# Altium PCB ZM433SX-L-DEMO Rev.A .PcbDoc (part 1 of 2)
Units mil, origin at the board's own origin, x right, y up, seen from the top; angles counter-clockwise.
Board outline 3937.01 x 2559.06 mil, 2 copper layers (Top Layer, Bottom Layer); 88 components, 121 nets, 406 pads, 438 vias.
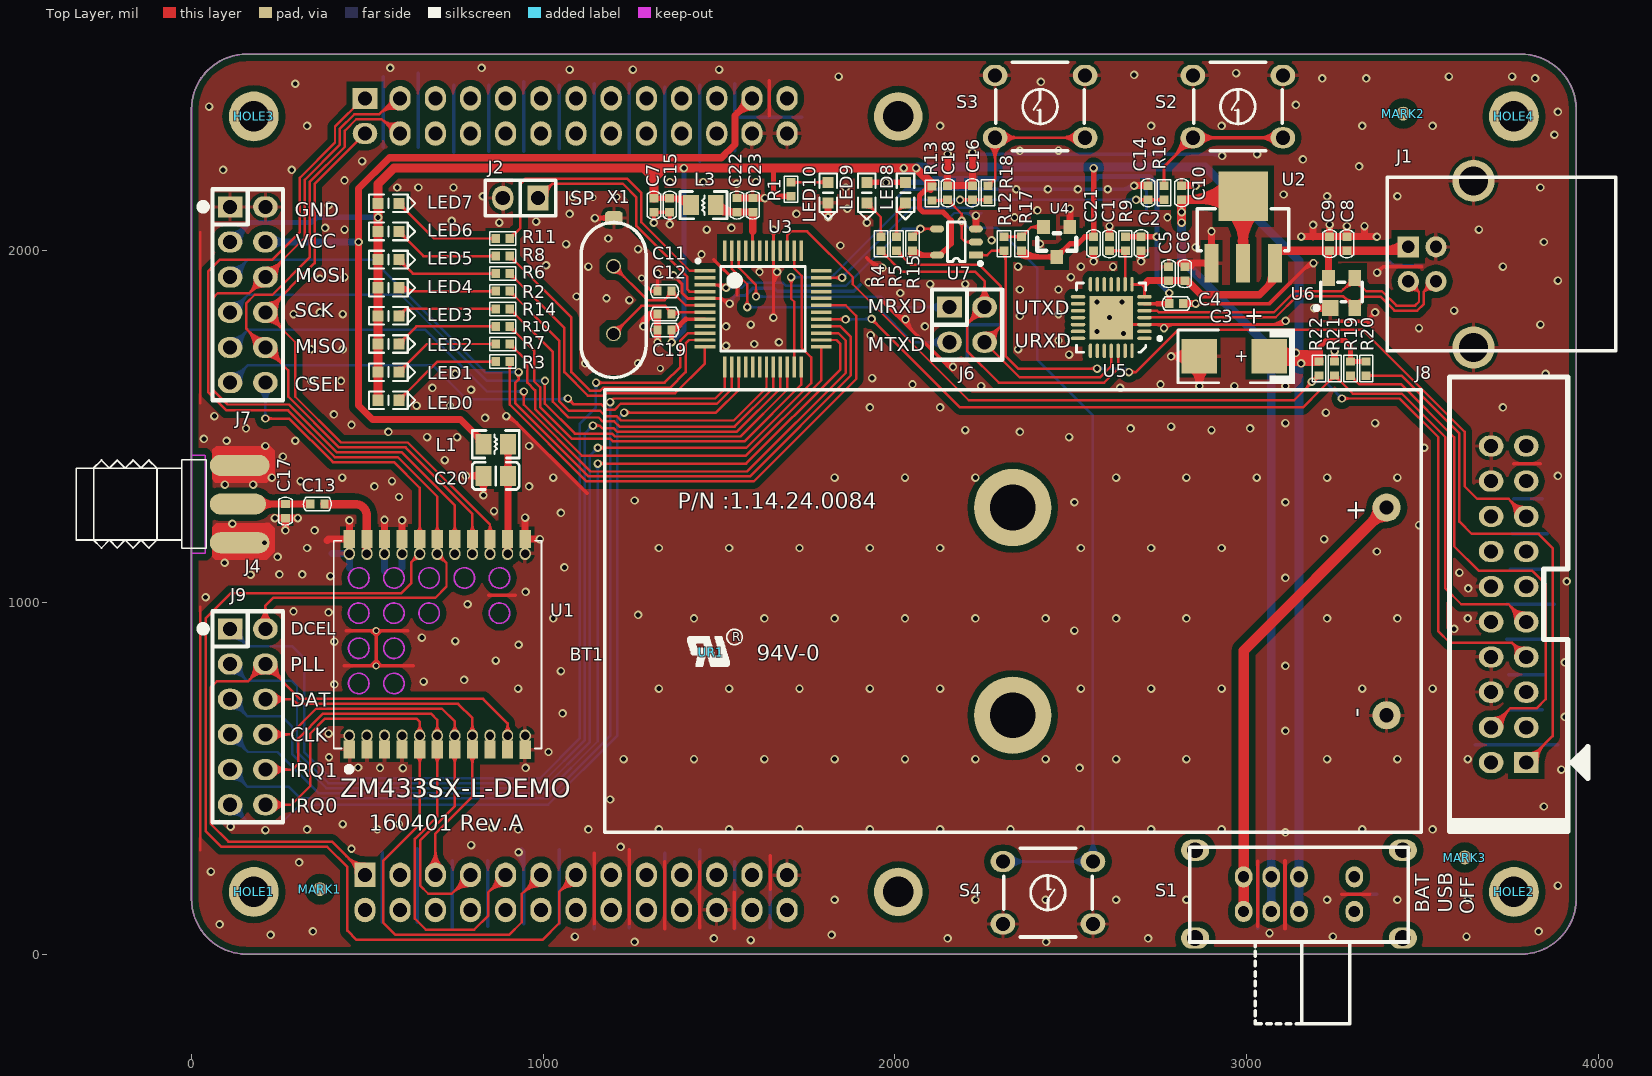
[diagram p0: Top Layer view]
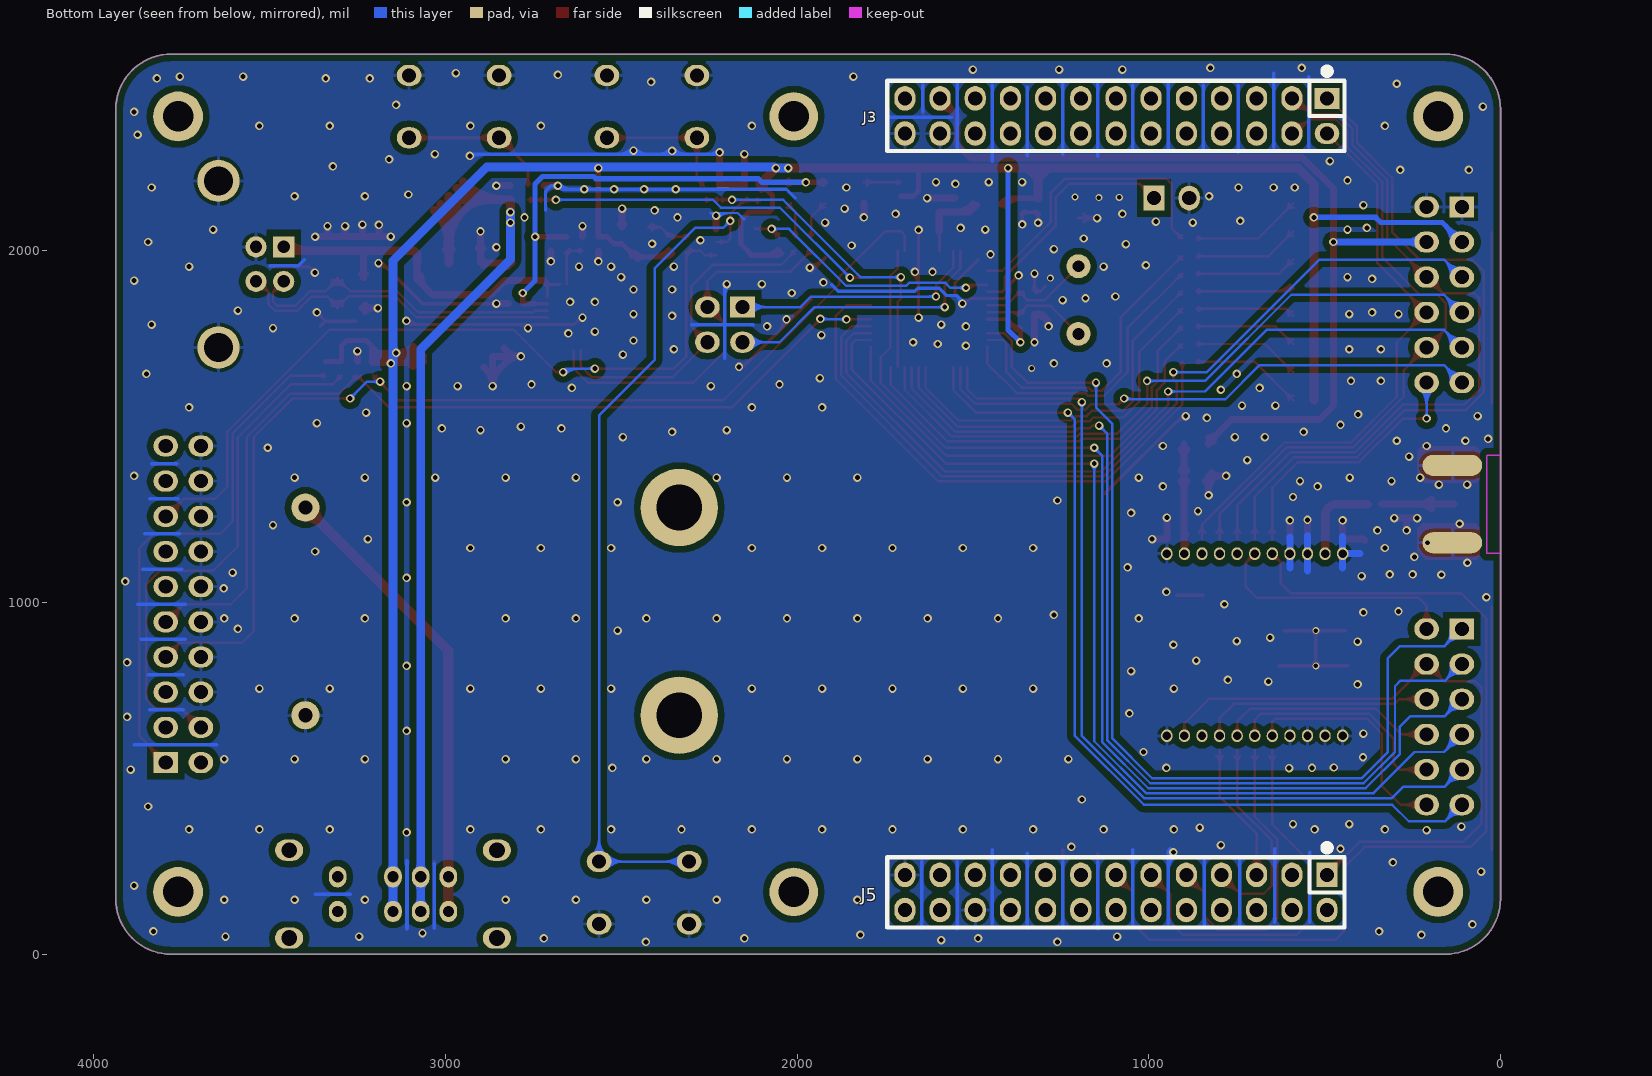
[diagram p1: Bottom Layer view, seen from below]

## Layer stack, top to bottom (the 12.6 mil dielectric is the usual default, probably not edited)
Top Layer: signal copper 1.4
Dielectric: dielectric 12.6, FR-4, Dk 4.8
Bottom Layer: signal copper 1.4

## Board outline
0,157.48 ccw(c157.48,157.48) 157.48,0 3779.52,0 ccw(c3779.52,157.48) 3937,157.48 3937.01,157.48 3937.01,2401.52 ccw(c3779.53,2401.52) 3779.53,2559 3779.53,2559.06 157.48,2559.06 ccw(c157.48,2401.58) 0,2401.58

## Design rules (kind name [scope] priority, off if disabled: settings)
AssemblyTestPointUsage [All] p1 off:
AssemblyTestpoint [All] p1 off: testpointundercomponent=TRUE minsize=40 maxsize=100 preferedsize=60 minholesize=0 maxholesize=40 preferedholesize=32 testpointgrid=1 usegrid=TRUE gridtolerance=0.01 allowsidetop=TRUE allowsidebottom=TRUE
Clearance Clearance_1 [inpoly] p1: gap=18
Clearance [All] p2: gap=7
ComponentClearance [All] p1 off: gap=10 collisioncheckmode=3 verticalgap=10 showdistances=FALSE
HoleSize [All] p1: absolutevalues=TRUE maxlimit=300 minlimit=1 maxpercent=80.000 minpercent=20.000
MinimumSolderMaskSliver [All] p1 off: minsoldermaskwidth=10
PolygonConnect PolygonConnect_1 [isvia] p1: connectstyle=Direct reliefconductorwidth=10 reliefentries=4 polygonreliefangle="90 Angle"
PolygonConnect [All] p2: connectstyle=Relief reliefconductorwidth=10 reliefentries=4 polygonreliefangle="90 Angle"
RoutingVias [All] p1: holewidth=28 width=50 viastyle="Through Hole" minholewidth=12 minwidth=20 maxholewidth=28 maxwidth=50
SilkToSilkClearance [All] p1 off: silktosilkclearance=10
SilkscreenOverComponentPads SilkToSolderMaskClearance [IsPad] p1 off: minsilkscreentomaskgap=10
SolderMaskExpansion [All] p1 off: expansion=4
Width [All] p1: maxlimit=80 minlimit=7 preferedwidth=7
21 further rules are at their usual default settings.

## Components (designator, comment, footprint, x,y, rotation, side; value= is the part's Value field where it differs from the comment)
BT1 "BATTERY" BAT-5#X2 2866.5,974.63 r270 top locked
C1 "1μF,±10%" 0402C 2610,2019.91 r270 top
C2 "1μF,±10%" 0402C 2700,2019.91 r90 top
C3 "100μF,10V" CAP-C 2965,1699.91 r180 top
C4 "0.1μF,±10%" 0402C 2800,1849.91 r0 top
C5 "1μF,±10%" 0402C 2778,1934.91 r90 top
C6 "0.01μF,±10%" 0402C 2824,1934.91 r90 top
C7 "0.1μF,±10%" 0402C 1314.67,2129.6 r270 top
C8 "0.01μF,±10%" 0402C 3285,2019.91 r270 top
C9 "1μF,±10%" 0402C 3235.84,2020.22 r90 top
C10 "1μF,±10%" 0402C 2815,2164.91 r90 top
C11 "20PF,±5%" 0402C 1345,1884.91 r180 top
C12 "20PF,±5%" 0402C 1345,1819.91 r180 top
C13 "220PF,±5%" 0402C 358,1279.91 r180 top
C14 "0.01μF,±10%" 0402C 2720,2164.91 r90 top
C15 "0.01μF,±10%" 0402C 1359.67,2129.6 r270 top
C16 "0.01μF,±10%" 0402C 2220,2164.91 r270 top
C17 "10PF,±0.5PF" 0402C 267,1259.91 r270 top
C18 "0.01μF,±10%" 0402C 2150,2164.91 r90 top
C19 "0.1μF,±10%" 0402C 1345,1774.91 r180 top
C20 "106,10μF" 0805C 865,1359.91 r180 top
C21 "0.01μF,±10%" 0402C 2565,2019.91 r90 top
C22 "0.1μF,±10%" 0402C 1550.75,2129.91 r90 top
C23 "0.01μF,±10%" 0402C 1595.75,2129.91 r270 top
HOLE1 "HOLE" HOLE-2.2#1 238.31,16.67 r0 top locked
HOLE2 "HOLE" HOLE-2.2#2 3759.84,177.17 r0 top locked
HOLE3 "HOLE" HOLE-2.2#2 177.17,2381.89 r0 top locked
HOLE4 "HOLE" HOLE-2.2#2 3759.84,2381.89 r0 top locked
J1 "USB" USB-B-1650X1105X1204 3552.28,1961.91 r90 top
J2 "CON2" SIP-2 935,2149.91 r180 top
J3 "HEADER 13X2" IDC-26#1 1093.31,2383.39 r0 bottom locked
J4 "BNC Connector3" BNC-2C 134.5,1279.91 r90 top locked
J5 "HEADER 13X2" IDC-26#2 1093.31,175.67 r0 bottom
J6 "HEADER 2X2" idc-4 2205,1789.91 r270 top locked
J7 "HEADER 6X2" idc-12 160,1874.91 r270 top locked
J8 "HEADER 10X2" IDE-20 3745,994.91 r90 top
J9 "HEADER 6X2" idc-12 160,674.91 r270 top
L1 "INDUCTOR1" L0805 865,1449.91 r180 top
L3 "INDUCTOR1" L0805 1455.51,2129.91 r0 top
LED0 "Power" LED-0603 560,1574.91 r0 top
LED1 "Power" LED-0603 560,1654.91 r0 top
LED2 "Power" LED-0603 560,1734.91 r0 top
LED3 "Power" LED-0603 560,1814.91 r0 top
LED4 "Power" LED-0603 560,1894.91 r0 top
LED5 "Power" LED-0603 560,1974.91 r0 top
LED6 "Power" LED-0603 560,2054.91 r0 top
LED7 "Power" LED-0603 560,2134.91 r0 top
LED8 "LED1" LED-0603 2030,2164.91 r270 top
LED9 "LED1" LED-0603 1920,2164.91 r270 top
LED10 "Power" LED-0603 1810,2164.91 r270 top
MARK1 "MARKER" MARKER-C-1.0M 365,184.91 r90 top
MARK2 "MARKER" MARKER-C-1.0M 3445,2389.91 r90 top
MARK3 "MARKER" MARKER-C-1.0M 3620,274.91 r90 top
R1 "2.7K,±5%" 0402R 1705,2174.91 r270 top
R2 "2.7K,±5%" 0402R 885,1884.91 r0 top
R3 "2.7K,±5%" 0402R 885,1684.91 r0 top
R4 "2.7K,±5%" 0402R 1960,2019.91 r90 top
R5 "2.7K,±5%" 0402R 2005,2019.91 r90 top
R6 "2.7K,±5%" 0402R 885,1934.91 r180 top
R7 "2.7K,±5%" 0402R 885,1734.91 r180 top
R8 "2.7K,±5%" 0402R 885,1984.91 r180 top
R9 "4.7K,±5%" 0402R 2655,2019.91 r90 top
R10 "2.7K,±5%" 0402R 885,1784.91 r180 top
R11 "2.7K,±5%" 0402R 885,2034.91 r180 top
R12 "2.7K,±5%" 0402R 2310,2019.91 r90 top
R13 "10K,±1%" 0402R 2105,2162.67 r270 top
R14 "2.7K,±5%" 0402R 885,1834.91 r180 top
R15 "10K,±1%" 0402R 2050,2019.91 r270 top
R16 "100Ω,±5%" 0402R 2765,2164.91 r270 top
R17 "10K,±1%" 0402R 2360,2019.91 r270 top
R18 "100Ω,±5%" 0402R 2265,2164.91 r90 top
R19 "10K,±1%" 0402R 3295,1664.91 r270 top
R20 "1.5K,±1%" 0402R 3340,1664.91 r270 top
R21 "10K,±1%" 0402R 3250.33,1665.2 r270 top
R22 "10K,±1%" 0402R 3205.33,1665.2 r270 top
S1 "SW DIP-4" SW2-3-2.0 3148.74,170.69 r90 top
S2 "SW-PB4P" KEY-6A 2975,2409.91 r0 top
S3 "SW-PB4P" KEY-6A 2412.69,2409.91 r0 top
S4 "SW-PB4P" KEY-6A 2435,174.91 r180 top
U1 "ZM470SX-M" ZM470SX-M 700,879.91 r90 top
U2 "SPX1117M3-L/TR" SOT-223 2990,2059.91 r90 top
U3 "LPC1114FBD48/302" QFP50P900X900X120-48N 1625,1834.91 r0 top locked
U4 "CAT810" SOT-23 2460,2024.91 r270 top (schematic designator U1)
U5 "CP2102" QFN50P500X500X100-29AN 2615,1809.91 r180 top
U6 "PRTR5V0U2X" SOT-143 3270,1879.91 r90 top
U7 "74AHC1G08" SOT-23-5 2175,2024.91 r180 top
UR1 "UR" ZY_UR-3X2 1476,858.91 r0 top
X1 "XTAL2" XTAL2-1120X470X3680 1200,1859.91 r90 top

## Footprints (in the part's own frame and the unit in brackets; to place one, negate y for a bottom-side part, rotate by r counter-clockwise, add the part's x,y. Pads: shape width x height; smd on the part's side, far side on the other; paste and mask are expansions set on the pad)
0402C [mm]
  rect 0.6x0.65 smd: 1(-0.508,0) 2(0.508,0)
  silkscreen extent -1.01,-0.48 1.01,0.48, body extent -0.51,-0.23 0.49,0.27, height 0.5
0402R [mm]
  rect 0.6x0.65 smd: 1(-0.508,0) 2(0.508,0)
  silkscreen extent -0.95,-0.48 0.95,0.48, body extent -0.47,-0.25 0.53,0.25, height 0.35
0805C [mm]
  rect 1.15x1.45 smd: 1(-0.889,0) 2(0.889,0)
  silkscreen extent -1.7,-0.99 1.7,0.99, body extent -1,-0.63 1,0.63, height 0.78
BAT-5#X2 [mil] "5#X2"
  round 220 hole 130: 0(-295.28,-531.5) 0(295.28,-531.5)
  round 80 hole 40: 1(-295.28,531.5) 2(295.28,531.5)
  silkscreen extent -630,-1691 628,630
BNC-2C [mil]
  oval 60x160 smd: 1(0,2.5)
  oval 60x170 smd: 2(-110,-2.5) 2(110,-2.5)
  oval 60x170 smd far side: 2(-110,-2.5) 2(110,-2.5)
  silkscreen extent -126,92 126,462
CAP-C [mm] "121120 改动了一点lsb"
  rect 2.55x2.5 smd: 1(-2.525,0) 2(2.525,0)
  silkscreen extent -4.39,-2.01 4.06,2.01, body extent -3.07,-1.6 3.13,1.6, height 2.6
HOLE-2.2#1 [mm]
  round 3.6 hole 2.2: 1(-1.553,4.077)
HOLE-2.2#2 [mm]
  round 3.6 hole 2.2: 1(0,0)
idc-4 [mil]
  rect 60x70 hole 40: 1(-50,-50)
  oval 60x70 hole 40: 2(-50,50) 3(50,-50) 4(50,50)
  silkscreen extent -100,-100 100,100, body extent -100,-100 100,100, height 298
idc-12 [mil]
  rect 60x70 hole 40: 1(-250,-50)
  oval 60x70 hole 40: 2(-250,50) 3(-150,-50) 4(-150,50) 5(-50,-50) 6(-50,50) 7(50,-50) 8(50,50) 9(150,-50) 10(150,50) 11(250,-50) 12(250,50)
  silkscreen extent -300,-136 300,100, body extent -300,-100 300,100, height 298
IDC-26#1 [mil]
  rect 70x60 hole 40: 1(-600,-50)
  oval 70x60 hole 40: 2(-600,50)
  oval 60x70 hole 40: 3(-500,-50) 4(-500,50) 5(-400,-50) 6(-400,50) 7(-300,-50) 8(-300,50) 9(-200,-50) 10(-200,50) 11(-100,-50) 12(-100,50) 13(0,-50) 14(0,50) 15(100,-50) 16(100,50) 17(200,-50) 18(200,50) 19(300,-50) 20(300,50) 21(400,-50) 22(400,50) 23(500,-50) 24(500,50) 25(600,-50) 26(600,50)
  silkscreen extent -650,-136 650,100, body extent -650,-100 650,100, height 298
IDC-26#2 [mil]
  rect 60x70 hole 40: 1(-600,-50)
  oval 60x70 hole 40: 2(-600,50) 3(-500,-50) 4(-500,50) 5(-400,-50) 6(-400,50) 7(-300,-50) 8(-300,50) 9(-200,-50) 10(-200,50) 11(-100,-50) 12(-100,50) 13(0,-50) 14(0,50) 15(100,-50) 16(100,50) 17(200,-50) 18(200,50) 19(300,-50) 20(300,50) 21(400,-50) 22(400,50) 23(500,-50) 24(500,50) 25(600,-50) 26(600,50)
  silkscreen extent -650,-136 650,100, body extent -650,-100 650,100, height 298
IDE-20 [mil] "原名：IDC-20IDE。by kong"
  rect 60x70 hole 40: 1(-450,-50)
  oval 60x70 hole 40: 2(-450,50) 3(-350,-50) 4(-350,50) 5(-250,-50) 6(-250,50) 7(-150,-50) 8(-150,50) 9(-50,-50) 10(-50,50) 11(50,-50) 12(50,50) 13(150,-50) 14(150,50) 15(250,-50) 16(250,50) 17(350,-50) 18(350,50) 19(450,-50) 20(450,50)
  silkscreen extent -646,-225 646,168, body extent -652,-178 647,176, height 346
KEY-6A [mil]
  oval 70x60 hole 40: 1(-127.95,88.58) 2(-127.95,-88.58) 3(127.95,-88.58) 4(127.95,88.58)
  silkscreen extent -126,-126 126,126, body extent -153,-122 152,122, height 273
L0805 [mm]
  rect 1.15x1.45 smd: 1(-0.889,0) 2(0.889,0)
  silkscreen extent -1.7,-0.99 1.7,0.99, body extent -1.02,-0.64 0.98,0.62, height 0.55
LED-0603 [mm] "20100324  贴片0603LED   LSB"
  rect 0.8x0.8 smd: 1(-0.75,0) 2(0.75,0)
  silkscreen extent -1.4,-0.64 1.93,0.64, body extent -0.8,-0.4 0.8,0.4, height 0.4
MARKER-C-1.0M [mm]
  round 1 smd paste-1.016 mask+0.5: 0(0,0)
  Top Layer pour cut-out: -1.1,0 -1.016,-0.421 -0.778,-0.778 -0.421,-1.016 0,-1.1 0,-1.1 0.421,-1.016 0.778,-0.778 1.016,-0.421 1.1,0 1.1,0 1.016,0.421 0.778,0.778 0.421,1.016 0,1.1 0,1.1 -0.421,1.016 -0.778,0.778 -1.016,0.421 -1.1,0
QFN50P500X500X100-29AN [mm]
  oval 1.05x0.25 smd: 1(-2.4,1.5) 2(-2.4,1) 3(-2.4,0.5) 4(-2.4,0) 5(-2.4,-0.5) 6(-2.4,-1) 7(-2.4,-1.5) 15(2.4,-1.5) 16(2.4,-1) 17(2.4,-0.5) 18(2.4,0) 19(2.4,0.5) 20(2.4,1) 21(2.4,1.5)
  oval 0.25x1.05 smd: 8(-1.5,-2.4) 9(-1,-2.4) 10(-0.5,-2.4) 11(0,-2.4) 12(0.5,-2.4) 13(1,-2.4) 14(1.5,-2.4) 22(1.5,2.4) 23(1,2.4) 24(0.5,2.4) 25(0,2.4) 26(-0.5,2.4) 27(-1,2.4) 28(-1.5,2.4)
  rect 3.15x3.15 smd paste-0.595: 29(0,0)
  silkscreen extent -3.63,-2.5 2.5,2.5
QFP50P900X900X120-48N [mm]
  rect 1.5x0.25 smd: 1(-4.2,2.75) 2(-4.2,2.25) 3(-4.2,1.75) 4(-4.2,1.25) 5(-4.2,0.75) 6(-4.2,0.25) 7(-4.2,-0.25) 8(-4.2,-0.75) 9(-4.2,-1.25) 10(-4.2,-1.75) 11(-4.2,-2.25) 12(-4.2,-2.75) 25(4.2,-2.75) 26(4.2,-2.25) 27(4.2,-1.75) 28(4.2,-1.25) 29(4.2,-0.75) 30(4.2,-0.25) 31(4.2,0.25) 32(4.2,0.75) 33(4.2,1.25) 34(4.2,1.75) 35(4.2,2.25) 36(4.2,2.75)
  rect 0.25x1.5 smd: 13(-2.75,-4.2) 14(-2.25,-4.2) 15(-1.75,-4.2) 16(-1.25,-4.2) 17(-0.75,-4.2) 18(-0.25,-4.2) 19(0.25,-4.2) 20(0.75,-4.2) 21(1.25,-4.2) 22(1.75,-4.2) 23(2.25,-4.2) 24(2.75,-4.2) 37(2.75,4.2) 38(2.25,4.2) 39(1.75,4.2) 40(1.25,4.2) 41(0.75,4.2) 42(0.25,4.2) 43(-0.25,4.2) 44(-0.75,4.2) 45(-1.25,4.2) 46(-1.75,4.2) 47(-2.25,4.2) 48(-2.75,4.2)
  silkscreen extent -4.82,-3.05 3.05,3.57, body extent -4.5,-4.5 4.5,4.5, height 1.2
SIP-2 [mil]
  rect 60x70 hole 40: 1(-50,0)
  oval 60x70 hole 40: 2(50,0)
  silkscreen extent -100,-50 100,50, body extent -100,-50 100,50, height 298
SOT-23 [mil]
  rect 40x36 smd: 1(-42.5,37.4) 2(-42.5,-37.4) 3(42.5,0)
  silkscreen extent -25,-56 25,56, body extent -47,-57 50,58, height 39
SOT-23-5 [mil]
  rect 40x20 smd: 1(-55,37.4)
  oval 40x20 smd: 2(-55,0) 3(-55,-37.4) 4(55,-37.4) 5(55,37.4)
  silkscreen extent -73,-57 26,66, body extent -55,-57 55,57, height 43
SOT-143 [mil] "SOT-143B"
  rect 46x46 smd: 1(-43,32.5)
  rect 46x36 smd: 2(-43,-37.5) 3(43,-37.5) 4(43,37.5)
  silkscreen extent -49,-58 30,77
SOT-223 [mil]
  rect 110x40 smd: 1(-95,90) 2(-95,0) 3(-95,-90)
  rect 140x140 smd: 4(95,0)
  silkscreen extent -60,-130 60,130, body extent -136,-128 138,128, height 65
SW2-3-2.0 [mil]
  oval 60x80 hole 45: 0(-125,295.28) 0(-125,-295.28) 0(125,295.28) 0(125,-295.28)
  oval 60x50 hole 32: 1(-49.21,-157.48) 2(-49.21,0) 3(-49.21,78.74) 4(-49.21,157.48) 5(49.21,-157.48) 6(49.21,0) 7(49.21,78.74) 8(49.21,157.48)
  silkscreen extent -368,-310 134,311
USB-B-1650X1105X1204 [mm]
  rect 1.524x1.524 hole 0.9: 1(1.25,2.355)
  round 1.524 hole 0.9: 2(-1.25,2.355) 3(-1.25,0.355) 4(1.25,0.355)
  round 3.048 hole 2.1: 5(-6.02,-2.355) 6(6.02,-2.355)
  silkscreen extent -6.27,-12.63 6.27,3.87, body extent -6.1,-12.76 6.1,3.24, height 11.49
XTAL2-1120X470X3680 [mil]
  round 42 / inner round 68 / far side round 68 hole 34: 1(-96.06,0) 2(96.06,0)
  rrect50% 40x50 smd paste-50: 3(233,-1)
  Top Layer pour cut-out: 56.06,20 76.06,40 116.06,40 136.06,20 136.06,-20 116.06,-40 76.06,-40 56.06,-20
  Top Layer pour cut-out: -136.06,20 -116.06,40 -76.06,40 -56.06,20 -56.06,-20 -76.06,-40 -116.06,-40 -136.06,-20
  silkscreen extent -221,-93 221,93, body extent -221,-89 231,95, height 138
ZM470SX-M [mil]
  rect 51.18x32 smd paste-19.68: 1(-298.29,251.28) 2(-298.29,201.28) 3(-298.29,151.28) 4(-298.29,101.28) 5(-298.29,51.28) 6(-298.29,1.28) 7(-298.29,-48.72) 8(-298.29,-98.72) 9(-298.29,-148.72) 10(-298.29,-198.72) 12(300.28,-248.72) 13(300.28,-198.72) 14(300.28,-148.72) 15(300.28,-98.72) 16(300.28,-48.72) 17(300.28,1.28) 18(300.28,51.28) 19(300.28,101.28) 20(300.28,151.28) 21(300.28,201.28) 22(300.28,251.28)
  oval 36x32 hole 24: 1(-258.94,251.28) 2(-258.94,201.28) 3(-258.94,151.28) 4(-258.94,101.28) 5(-258.94,51.28) 6(-258.94,1.28) 7(-258.94,-48.72) 8(-258.94,-98.72) 9(-258.94,-148.72) 10(-258.94,-198.72) 11(-258.94,-248.72) 12(258.94,-248.72) 13(258.94,-198.72) 14(258.94,-148.72) 15(258.94,-98.72) 16(258.94,-48.72) 17(258.94,1.28) 18(258.94,51.28) 19(258.94,101.28) 20(258.94,151.28) 21(258.94,201.28) 22(258.94,251.28)
  rect 52x32 smd paste-19.68: 11(-298.7,-248.72)
  Top Layer keep-out circle w5: c189.84,224.34 r29.05
  Top Layer keep-out circle w5: c89.84,224.34 r29.05
  Top Layer keep-out circle w5: c-10.16,224.34 r29.05
  Top Layer keep-out circle w5: c-110.16,224.34 r29.05
  Top Layer keep-out circle w5: c-110.16,124.34 r29.05
  Top Layer keep-out circle w5: c-10.16,124.34 r29.05
  Top Layer keep-out circle w5: c89.84,124.34 r29.05
  Top Layer keep-out circle w5: c189.84,124.34 r29.05
  Top Layer keep-out circle w5: c89.84,24.34 r29.05
  Top Layer keep-out circle w5: c189.84,24.34 r29.05
  Top Layer keep-out circle w5: c189.84,-75.66 r29.05
  Top Layer keep-out circle w5: c89.84,-175.66 r29.05
  Top Layer keep-out circle w5: c189.84,-175.66 r29.05
  silkscreen extent -361,-295 295,295
ZY_UR-3X2 [mil]
  silkscreen extent -67,-40 90,65

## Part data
BT1: library part 1.06.10.0016, "BT-12M1.3AT,DV1.2Ah,97×44×52mm,福建泉州赛特"
C1 C2 C5 C9 C10: library part 1.02.17.0007, "1μF,±10%,6.3V,X5R,0402,RoHS"
C3: library part 1.02.05.0016, "100μF,10V,C型,,AVX,RoHS"
C4 C7 C19 C22: library part 1.02.17.0020, "0.1μF,±10%,X5R,25V,0402,RoHS"
C6 C8 C14 C15 C16 C18 C21 C23: library part 1.02.17.0019, "0.01μF,±10%,X7R,50V,0402,RoHS"
C11 C12: library part 1.02.17.0009, "20PF,±5%,50V,COG,0402,RoHS"
C13: library part 1.02.17.0035, "220PF,±5%,50V,NPO,0402,RoHS"
C17: library part 1.02.17.0008, "10PF,±0.5PF,50V,COG,0402,TDK,RoHS"
C20: library part 1.02.02.0055, "106,10μF,±10%,10V,X5R,0805,RoHS"
J1: library part 1.10.05.0010, "USB-B,12.2×16.4×11,90°,RoHS"
J2: library part 1.10.03.0084, "2.54mm,1×2,180°,H=8.5mm,2.4/3.0,镀全金3U,,RoHS"
J4: library part 1.10.05.0129, "SMA,外螺纹,孔,SMD,RoHS"
J8: library part 1.10.04.0003, "简易牛角座,20P,180°,黑色,,*"
L1 L3: library part 1.03.03.0020, "HCB2012KF-121T20,0805,信和达,RoHS"
LED0 LED1 LED2 LED3 LED4 LED5 LED6 LED7 LED10: library part 1.04.05.0008, "红色,0603,0603,*,RoHS"
LED8 LED9: library part 1.04.05.0009, "绿色,0603,0603,*,RoHS"
R1 R2 R3 R4 R5 R6 R7 R8 R10 R11 R12 R14: library part 1.01.17.0062, "2.7K,±5%,1/16W,0402,RoHS"
R9: library part 1.01.17.0019, "4.7K,±5%,0402,RALEC,RoHS"
R13 R15 R17 R19 R21 R22: library part 1.01.17.0034, "10K,±1%,0402,RALEC,RoHS"
R16 R18: library part 1.01.17.0012, "100Ω,±5%,0402,RALEC,RoHS"
R20: library part 1.01.17.0011, "1.5K,±1%,0402,RALEC,RoHS"
S1: library part 1.09.07.0014, "16×7.0×12.5mm,柄长6.0mm,单刀三掷开关"
S2 S3: library part 1.09.02.0001, "6×6×4.3mm,,*"
S4: library part 1.09.02.0012, "6×6×11mm"
U1: library part ZM470SX-E
U2: library part 1.05.09.0025, "SPX1117M3-L-3.3,SOT-223,EXAR,RoHS"
U3: library part 1.05.02.0118, "LPC1114FBD48/302,LQFP-48,NXP,RoHS"
U4: library part 1.05.07.0029, "CAT809RTBI-GT3,SOT23,ON,RoHS"
U5: library part 1.05.08.0037, "CP2102GMR,QFN-28,Silicon Labs"
U6: library part 1.05.10.0153, "PRTR5V0U2X,SOT-143B,NXP,RoHS"
U7: library part 1.05.05.0093, "74AHC1G08GV,SOT-753,NXP,RoHS"
X1: library part 1.07.02.0010, "11.0592MHz,±30ppm,20pF,-40~85℃,±30ppm,HC-49/S,*,RoHS"

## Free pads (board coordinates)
  round 137.8 hole 86.61: 1(2009.45,177.17) 1(2009.45,2381.89)

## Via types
v1: diameter 24, hole 14, Top Layer to Bottom Layer, tented both sides, 426 vias
v2: diameter 20, hole 12, Top Layer to Bottom Layer, tented both sides, 7 vias
v3: diameter 24, hole 14, Top Layer to Bottom Layer, tented bottom, 5 vias

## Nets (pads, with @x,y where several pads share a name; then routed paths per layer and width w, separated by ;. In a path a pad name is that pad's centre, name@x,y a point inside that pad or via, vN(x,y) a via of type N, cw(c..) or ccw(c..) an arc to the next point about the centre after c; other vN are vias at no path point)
ADC0: J5.19
ADC1: J5.20
ADC6: J5.17
AGND: BT1.2 C1.1 C2.1 C3.2 C4.2 C5.2 C6.2 C7.2 C8.1 C9.2 C10.2 C11.2 C12.2 C14.2 C15.2 C16.1 C17.2 C18.2 C19.2 C20.2 C21.1 C22.2 C23.1 J1.4 J1.5 J1.6 J2.2 J3.24 J3.26 J4.2 J5.22 J5.25 J7.1 J7.2 J8.6 J8.8 J8.10 J8.12 J8.14 J8.16 J8.18 J8.20 LED10.2 R21.1 S2.1 S2.4 S3.1 S3.4 S4.1 S4.4 U1.1 U1.2 U1.3 U1.4 U1.11 U1.12 U1.19 U1.20 U1.22 U2.1 U3.5 U3.41 U4.1 U5.3 U5.29 U6.1 U7.3 X1.3 | length 20500.1
  Top Layer w7: 25,294.91 25,987.91 ; 25,1566.91 25,2052.91
  Top Layer w9: v1(1147,2092.91) X1.3@1201,2092.91 ; v1@1150.75,2086.41 cw(c1164.92,2061.87) 1172.25,2089.24 ; v1@1150.75,2099.4 ccw(c1164.92,2123.94) 1172.25,2096.57 ; v1@1152.3,2087.6 cw(c1165.11,2074.8) 1165.11,2092.91 cw(c1165.11,2111.01) v1@1152.3,2098.21 ; X1.3@1185.04,2081.95 ccw(c1158.58,2055.49) 1158.58,2092.91 ccw(c1158.58,2130.33) X1.3@1185.04,2103.87 ; 1293,1899.91 1308,1884.91 ; v1@1309.37,2084.88 ccw(c1296.56,2097.69) 1314.67,2097.69 ccw(c1332.78,2097.69) v1@1319.97,2084.88 ; C7.2@1309.5,2104.43 cw(c1297.02,2091.95) 1314.67,2091.95 cw(c1332.32,2091.95) C7.2@1319.84,2104.43 ; v1(1314.67,2079.58) C7.2@1314.67,2109.6 C15.2@1359.67,2109.6 v1(1359.67,2075.24) ; C11.2@1319.69,1879.88 ccw(c1308,1868.8) 1308,1884.91 ; C11.2@1319.69,1889.94 cw(c1308,1901.01) 1308,1884.91 ; v1@1319.7,1929.6 cw(c1306.89,1916.8) 1325,1916.8 cw(c1343.11,1916.8) v1@1330.3,1929.6 ; C11.2@1319.83,1891.06 ccw(c1307.35,1903.54) 1325,1903.54 ccw(c1342.65,1903.54) C11.2@1330.17,1891.06 ; C7.2@1320.83,2104.43 cw(c1333.31,2091.95) 1333.31,2109.6 cw(c1333.31,2127.25) C7.2@1320.83,2114.77 ; v1(1325,1934.91) C11.2@1325,1884.91 1308,1884.91 ; C15.2@1353.52,2104.43 ccw(c1341.04,2091.95) 1341.04,2109.6 ccw(c1341.04,2127.25) C15.2@1353.52,2114.77 ; v1@1354.37,2080.54 ccw(c1341.56,2093.34) 1359.67,2093.34 ccw(c1377.78,2093.34) v1@1364.97,2080.54 ; C15.2@1354.5,2104.43 cw(c1342.02,2091.95) 1359.67,2091.95 cw(c1377.32,2091.95) C15.2@1364.84,2104.43 ; v1@1370,1922.41 cw(c1370,1904.3) 1382.8,1917.1 cw(c1395.61,1929.91) v1@1377.5,1929.91 ; v1(1370,1929.91) 1395,1904.91 1395,1879.91 1410.47,1864.43 U3.5@1459.65,1864.43 1506.47,1864.43 ; 1485,1974.91 1551,1908.91 1551,1874.91 ; v1@1528.76,1857.3 cw(c1524.54,1882.5) 1506.47,1864.43 ; v1(1530,1849.91) 1521,1849.91 1506.47,1864.43 ; v1@1649.22,1815.21 ccw(c1636.42,1828.01) 1654.53,1828.01 ccw(c1672.63,1828.01) v1@1659.83,1815.21 ; v1@1649.22,2054.13 cw(c1636.42,2041.33) 1654.53,2041.33 cw(c1672.63,2041.33) v1@1659.83,2054.13 ; v1@1654.53,1804.43 v1(1654.53,1809.91) U3.41@1654.53,2000.26 v1(1654.53,2059.43) ; 1654.53,1896.52 cw(c1708.39,1896.52) v1@1670.3,1934.6 ; 1654.53,1918.25 cw(c1686.66,1918.25) v1@1663.94,1940.97 ; 1654.53,1961.57 ccw(c1686.66,1961.57) v1@1663.94,1938.85 ; U5.29@2610,1802.41 cw(c2610,1772.23) U5.29@2631.34,1793.57 ; U5.29@2615,1809.91 2634.68,1790.22 U5.3@2709.49,1790.22 2754.68,1790.22 ; 2743.72,1790.22 cw(c2743.72,1758.63) v1@2766.06,1780.97 ; v1@2757.6,1781.13 ccw(c2747.31,1782.84) 2754.69,1790.22 ; v1@2763.58,1780.38 cw(c2777.21,1775.85) 2777.21,1790.22 ; v1@2763.59,1780.42 cw(c2777.14,1775.48) 2777.14,1789.91 ; v1@2763.77,1787.31 cw(c2762.06,1797.6) 2754.69,1790.22 ; v1@2766.42,1787.27 ccw(c2768.22,1796.68) 2775,1789.91 ; v1@2772.05,1777.34 cw(c2790,1770.8) 2790,1789.91 ; v1@2772.12,1777.54 cw(c2789.68,1771.71) 2789.68,1790.22 ; v1@2772.37,1781.32 cw(c2781.77,1783.13) 2775,1789.91 ; 3066.34,1789.91 ccw(c3066.34,1845.57) v1@3105.7,1806.21 ; 3088.06,1789.91 ccw(c3088.06,1823.84) v1@3112.06,1799.85 ; v1@3103.55,1800.06 cw(c3091.24,1798.66) 3100,1789.91 ; v1@3110.15,1793.45 ccw(c3108.76,1781.15) 3100,1789.91 ; v1@3115,1804.91 3100,1789.91 ; 2754.68,1790.22 2789.68,1790.22 ; 2754.68,1790.22 v1(2765,1779.91) 2775,1789.91 ; 2775,1789.91 2790,1789.91 ; 2789.68,1790.22 2790,1789.91 ; 2790,1789.91 3100,1789.91
  Top Layer w10: 435,819.91 510,819.91 ; 440,919.91 510,919.91 ; 545,919.91 540,919.91 ; 615,919.91 540,919.91 ; 630,819.91 540,819.91 ; 845,1019.91 920,1019.91 ; v1@895,1522.91 cw(c895,1481.87) 924.02,1510.89 ; v1(895,1529.91) 905,1529.91 1125,1309.91 ; v1@895,1532.91 cw(c895,1516.01) 906.95,1527.96 ; 1145,87.19 1145,287.19 ; 1245,87.19 1245,297.19 ; 1345,72.19 1345,262.19 ; 1445,75.67 1445,262.19 ; 1543.31,73.89 1543.31,175.67 ; 1643.31,2383.39 1643.31,2483.38 ; 1645,184.91 1645,279.91 ; 1920,1979.91 1960,1939.91 ; 1924.74,1975.17 ccw(c1964,2014.43) v1@1964,1958.91 ; 1941.81,1958.1 ccw(c1964,1980.29) v1@1964,1948.91 ; 1960,1862.36 v1@2162.46,1659.91 ; 1996.64,1825.73 ccw(c2030,1859.09) v1@2030,1811.91 ; 2013.71,1808.66 ccw(c2030,1824.95) v1@2030,1801.91 ; v1@2027,1804.91 ccw(c2050.04,1804.91) 2033.75,1788.62 ; v1@2037,1804.91 ccw(c2084.18,1804.91) 2050.82,1771.54 ; 2131.64,1690.73 ccw(c2165,1724.09) v1@2165,1676.91 ; 2148.71,1673.65 ccw(c2165,1689.95) v1@2165,1666.91 ; v1(2855,1849.91) 3065,1849.91 3185,1969.91 v1@3190,1969.91 ; v1@2859.95,1844.96 cw(c2871.9,1833.01) 2871.9,1849.91 cw(c2871.9,1866.81) v1@2859.95,1854.86 ; 3031,79.91 3031,263.91 ; 3109,72.91 3109,265.91 ; 3160.98,1945.89 cw(c3190,1916.87) v1@3190,1957.91 ; 3178.05,1962.96 cw(c3190,1951.01) v1@3190,1967.91 ; 3255,1799.91 3340,1799.91 ; 3270,169.91 3350,169.91 ; 3356,1785.91 3342,1799.91 3340,1799.91 ; v1@3358,1824.91 cw(c3341.1,1824.91) 3353.05,1812.96 cw(c3365,1801.01) v1@3365,1817.91 ; v1(3365,1824.91) 3340,1799.91 ; v1(3371,1937.91) 3388,1954.91 3498,1954.91 ; v1@3371,1944.91 ccw(c3371,1961.81) 3382.95,1949.86 ccw(c3394.9,1937.91) v1@3378,1937.91 ; 3760,1394.91 3835,1394.91 ; 510,819.91 v2(525,819.91) ; 510,819.91 525,834.91 ; 510,919.91 v2(525,919.91) ; 510,919.91 525,904.91 ; 512.93,819.91 cw(c512.93,807.84) v2@521.46,816.37 ; 512.93,819.91 ccw(c512.93,831.98) v2@521.46,823.44 ; 512.93,819.91 cw(c512.93,807.84) v2@521.46,816.37 ; 512.93,819.91 ccw(c512.93,831.98) v2@521.46,823.44 ; 512.93,819.91 cw(c512.93,807.84) v2@521.46,816.37 ; 512.93,819.91 ccw(c512.93,831.98) v2@521.46,823.44 ; 512.93,919.91 cw(c512.93,907.84) v2@521.46,916.37 ; 512.93,919.91 ccw(c512.93,931.98) v2@521.46,923.44 ; 512.93,919.91 cw(c512.93,907.84) v2@521.46,916.37 ; 512.93,919.91 ccw(c512.93,931.98) v2@521.46,923.44 ; 512.93,919.91 cw(c512.93,907.84) v2@521.46,916.37 ; 512.93,919.91 ccw(c512.93,931.98) v2@521.46,923.44 ; v2@521.46,823.44 ccw(c512.93,831.98) 525,831.98 ; v2@521.46,823.44 ccw(c512.93,831.98) 525,831.98 ; v2@521.46,823.44 ccw(c512.93,831.98) 525,831.98 ; v2@521.46,916.37 cw(c512.93,907.84) 525,907.84 ; v2@521.46,916.37 cw(c512.93,907.84) 525,907.84 ; v2@521.46,916.37 cw(c512.93,907.84) 525,907.84 ; v2(525,819.91) 540,819.91 ; v2(525,819.91) 525,834.91 ; 525,831.98 ccw(c537.07,831.98) v2@528.54,823.44 ; 525,831.98 ccw(c537.07,831.98) v2@528.54,823.44 ; 525,831.98 ccw(c537.07,831.98) v2@528.54,823.44 ; 525,834.91 525,904.91 ; 525,834.91 540,819.91 ; 525,904.91 v2(525,919.91) ; 525,904.91 540,919.91 ; 525,907.84 cw(c537.07,907.84) v2@528.54,916.37 ; 525,907.84 cw(c537.07,907.84) v2@528.54,916.37 ; 525,907.84 cw(c537.07,907.84) v2@528.54,916.37 ; v2(525,919.91) 540,919.91 ; v2@528.54,816.37 cw(c537.07,807.84) 537.07,819.91 ; v2@528.54,816.37 cw(c537.07,807.84) 537.07,819.91 ; v2@528.54,816.37 cw(c537.07,807.84) 537.07,819.91 ; v2@528.54,823.44 ccw(c537.07,831.98) 537.07,819.91 ; v2@528.54,823.44 ccw(c537.07,831.98) 537.07,819.91 ; v2@528.54,823.44 ccw(c537.07,831.98) 537.07,819.91 ; v2@528.54,916.37 cw(c537.07,907.84) 537.07,919.91 ; v2@528.54,916.37 cw(c537.07,907.84) 537.07,919.91 ; v2@528.54,916.37 cw(c537.07,907.84) 537.07,919.91 ; v2@528.54,916.37 cw(c537.07,907.84) 537.07,919.91 ; v2@528.54,916.37 cw(c537.07,907.84) 537.07,919.91 ; v2@528.54,923.44 ccw(c537.07,931.98) 537.07,919.91 ; v2@528.54,923.44 ccw(c537.07,931.98) 537.07,919.91 ; v2@528.54,923.44 ccw(c537.07,931.98) 537.07,919.91 ; v2@528.54,923.44 ccw(c537.07,931.98) 537.07,919.91 ; v2@528.54,923.44 ccw(c537.07,931.98) 537.07,919.91
  Top Layer w20: v1(237,1239.91) C17.2@267,1239.91 ; v1(267,1204.91) C17.2@267,1239.91 ; v1(302,1239.91) C17.2@267,1239.91 ; 386,1175.91 390.28,1180.18 U1.22@448.72,1180.18 v1(448.72,1233.63) ; U1.20@548.72,1180.18 v1(548.72,1234.91) ; U1.19@598.72,1180.18 v1(598.72,1233.63) ; v1(780,1359.91) C20.2@830,1359.91 v1(830,1304.91) ; C20.2@821.06,1345.07 cw(c799.49,1323.49) 830,1323.49 cw(c860.51,1323.49) C20.2@838.94,1345.07 ; C20.2@821.06,1350.97 ccw(c799.49,1329.4) 799.49,1359.91 ccw(c799.49,1390.42) C20.2@821.06,1368.84 ; v1(948.72,1241.18) U1.12@948.72,1180.18 v1(990.27,1180.18) ; v1@1286.8,1785.78 cw(c1301.81,1793.1) 1290,1804.91 ; v1@1287,1784.91 cw(c1328.04,1784.91) 1299.02,1813.93 ; C12.2@1324.8,1817.12 ccw(c1320.11,1774.79) 1290,1804.91 ; v1(1325,1739.91) C19.2@1325,1774.91 C12.2@1325,1819.91 1305,1819.91 1290,1804.91 ; C22.2@1550.75,2149.91 C23.1@1595.75,2149.91 v1(1630,2149.91) ; v1(1810,2094.91) LED10.2@1810,2135.38 ; v1(2150,2274.91) C18.2@2150,2184.91 C16.1@2220,2184.91 v1@2220,2269.91 ; U7.3@2230,2062.31 v1(2230,2099.91) ; U4.1@2491.74,2075.06 ccw(c2478.09,2088.72) 2497.4,2088.72 ccw(c2516.72,2088.72) U4.1@2503.06,2075.06 ; U4.1@2497.4,2067.41 v1(2497.4,2119.91) ; v1(2565,1969.91) C21.1@2565,1999.91 ; C1.1@2610,2039.91 v1(2610,2069.91) ; v1(2680,2184.91) C14.2@2720,2184.91 ; v1(2700,1969.91) C2.1@2700,1999.91 ; C10.2@2815,2184.91 v1(2855,2184.91) ; C4.2@2820,1849.91 v1(2855,1849.91) ; C6.2@2821.21,1954.73 ccw(c2810,1953.64) 2810,1964.91 U2.1@2900,1964.91 v1(2900,2054.91) ; C6.2@2826.26,1953.63 cw(c2853.5,1926.39) 2853.5,1964.91 ; C6.2@2832.04,1964.91 cw(c2832.04,1955.78) 2841.12,1956.67 ; C3.2@2833.52,1676.01 ccw(c2785,1638.72) v1(2785,1699.91) ; C3.2@2833.52,1723.81 cw(c2785,1761.1) v1(2785,1699.91) ; C3.2@2840.14,1670.08 cw(c2793.08,1614.91) v1(2865.59,1614.91) ; C3.2@2891.04,1670.08 ccw(c2938.1,1614.91) v1(2865.59,1614.91) ; U2.1@2892.93,1957.84 ccw(c2875.86,1940.76) 2875.86,1964.91 ccw(c2875.86,1989.05) U2.1@2892.93,1971.98 ; U2.1@2892.93,2006.98 ccw(c2875.86,2024.05) 2900,2024.05 ccw(c2924.14,2024.05) U2.1@2907.07,2006.98 ; v1(3155.31,2040.22) C9.2@3235.84,2040.22 ; 3188.78,2039.59 v1(3188.78,2073.44) ; v1(3192,1836.91) U6.1@3237.5,1836.91 ; U6.1@3228.31,1827.71 ccw(c3206.12,1805.52) 3206.12,1836.91 ccw(c3206.12,1868.29) U6.1@3228.31,1846.1 ; v1(3235.84,2074.07) C9.2@3235.84,2040.22 ; R21.1@3250.33,1685.2 v1(3250.33,1714.57) ; C8.1@3285,2039.91 C8.1@3285,2040.22 ; v1(3285,2069.91) C8.1@3285,2040.22 ; v1(3335,2069.91) 3335,2039.91 ; v1(3370,2039.91) 3335,2039.91 ; v1(2785,1699.91) C3.2@2865.59,1699.91 v1(2865.59,1614.91) ; C9.2@3235.84,2040.22 C8.1@3285,2040.22 ; C8.1@3285,2040.22 3334.69,2040.22 3335,2039.91
  Bottom Layer w7: 2150.5,2089.41 2168.5,2107.41 2247.5,2107.41 ccw(c2247.5,2098.34) v1@2238.47,2099.15 ; 2191.37,2107.41 cw(c2191.37,2061.28) v1@2223.99,2093.9 ; 2208.27,2107.41 cw(c2208.27,2078.18) v1@2228.94,2098.85 ; v1@2231.49,2099.77 cw(c2239.84,2099.02) 2239.84,2107.41
  Bottom Layer w9: 1534.08,1861.2 1545.29,1872.41 ; v1@1537.47,1850.63 cw(c1564.47,1853.22) 1545.29,1872.41 ; 1901.5,1903.41 1883,1884.91 1665,1884.91 1656.5,1893.41 1595.27,1893.41 1574.27,1872.41 1545.29,1872.41 ; 2005,2149.91 2030,2174.91 2670,2174.91 v1(2680,2184.91) 2700,2184.91 2715,2169.91 2715,2114.91 ; v1@2339.7,2169.6 ccw(c2326.89,2156.8) 2326.89,2174.91 ccw(c2326.89,2193.01) v1@2339.7,2180.21 ; v1@2350.3,2169.6 cw(c2363.11,2156.8) 2363.11,2174.91 cw(c2363.11,2193.01) v1@2350.3,2180.21 ; v1@2429.7,2169.6 ccw(c2416.89,2156.8) 2416.89,2174.91 ccw(c2416.89,2193.01) v1@2429.7,2180.21 ; v1@2440.3,2169.6 cw(c2453.11,2156.8) 2453.11,2174.91 cw(c2453.11,2193.01) v1@2440.3,2180.21 ; v1@2514.7,2169.6 ccw(c2501.89,2156.8) 2501.89,2174.91 ccw(c2501.89,2193.01) v1@2514.7,2180.21 ; v1@2525.3,2169.6 cw(c2538.11,2156.8) 2538.11,2174.91 cw(c2538.11,2193.01) v1@2525.3,2180.21 ; v1@2599.7,2169.6 ccw(c2586.89,2156.8) 2586.89,2174.91 ccw(c2586.89,2193.01) v1@2599.7,2180.21 ; v1@2610.3,2169.6 cw(c2623.11,2156.8) 2623.11,2174.91 cw(c2623.11,2193.01) v1@2610.3,2180.21 ; 2637.75,2174.91 ccw(c2637.75,2227.16) v1@2674.7,2190.21 ; 2659.48,2174.91 ccw(c2659.48,2205.43) v1@2681.06,2183.85 ; v1@2685.3,2179.6 cw(c2698.11,2166.8) 2698.11,2184.91 cw(c2698.11,2203.01) v1@2685.3,2190.21
  Bottom Layer w10: 541.69,90.5 541.69,290.5 ; 545,2294.91 545,2494.91 ; 641.69,90.5 641.69,300.5 ; 645,2294.91 645,2504.91 ; 741.69,75.5 741.69,265.5 ; 745,2279.91 745,2469.91 ; 841.69,78.98 841.69,265.5 ; 845,2283.39 845,2469.91 ; v1@925.05,284.96 cw(c876.89,236.79) 945,236.79 ; v1@932.12,292.03 cw(c901.03,260.94) 945,260.94 ; 939.19,299.1 cw(c925.17,285.08) 945,285.08 ; 945,87.19 945,287.19 ; 945,2283.39 945,2479.91 ; 1045,87.19 1045,297.19 ; 1045,2289.91 1045,2469.91 ; 1145,72.19 1145,262.19 ; 1145,2269.41 1145,2474.91 ; 1245,75.67 1245,262.19 ; 1245,2274.41 1245,2474.91 ; 1345,87.19 1345,287.19 ; 1345,2269.91 1345,2464.91 ; 1445,87.19 1445,297.19 ; 1445,2254.91 1445,2469.91 ; 1545,72.19 1545,262.19 ; 1545,2284.91 1545,2474.91 ; 1560,2379.91 1735,2379.91 ; 1643.31,2395.6 1643.31,2469.91 ; 1645,75.67 1645,262.19 ; 2125,1789.91 2205,1789.91 ; v1@2195.05,1899.96 cw(c2171.03,1875.94) 2205,1875.94 ; v1(2200,1904.91) 2205,1899.91 2205,1789.91 ; 2205,1693.91 2205,1789.91 ; v1@2224.95,2284.86 ccw(c2251.38,2311.29) 2251.38,2273.91 ; v1@2226.98,2280.42 ccw(c2234,2280.95) 2234,2273.91 2926,2273.91 v1(2930,2269.91) ; 2300,1789.91 2205,1789.91 ; 2313.92,2273.91 ccw(c2313.92,2325) v1@2350.05,2288.87 ; 2338.06,2273.91 ccw(c2338.06,2300.86) v1@2357.12,2281.8 ; 2345.81,2274.73 ccw(c2347.8,2276.72) 2347.8,2273.91 ; v1@2352.88,2281.8 ccw(c2371.94,2300.86) 2371.94,2273.91 ; v1@2359.95,2288.87 ccw(c2396.08,2325) 2396.08,2273.91 ; 2362.2,2273.91 ccw(c2362.2,2276.72) 2364.19,2274.73 ; 2421.54,2273.91 ccw(c2421.54,2328.36) v1@2460.05,2289.86 ; 2445.69,2273.91 ccw(c2445.69,2304.22) v1@2467.12,2282.79 ; 2455.81,2275.71 ccw(c2460.17,2280.08) 2460.17,2273.91 ; v1@2462.88,2282.79 ccw(c2484.31,2304.22) 2484.31,2273.91 ; 2469.83,2273.91 ccw(c2469.83,2280.08) 2474.19,2275.71 ; v1@2469.95,2289.86 ccw(c2508.46,2328.36) 2508.46,2273.91 ; 2903.44,2273.91 cw(c2903.44,2243.35) v1@2925.05,2264.96 ; 3031,73.91 3031,256.91 ; 3109,72.91 3109,265.91 ; 3270,169.91 3370,169.91 ; 3401,1974.91 3418,1957.91 3498,1957.91 ; 3650,594.91 3885,594.91 ; 3740,894.91 3865,894.91 ; 3740,994.91 3875,994.91 ; 3745,694.91 3840,694.91 ; 3745,794.91 3845,794.91 ; 3750,1094.91 3860,1094.91 ; 3755,1194.91 3855,1194.91 ; 3760,1294.91 3840,1294.91 ; 3765,1394.91 3835,1394.91
  Bottom Layer w20: 400.06,1138.85 U1.22@448.72,1138.85 ; 448.72,1097.63 U1.22@448.72,1138.85 ; 448.72,1187.91 U1.22@448.72,1138.85 ; 548.72,1089.63 U1.20@548.72,1138.85 548.72,1190.63 ; 598.72,1097.63 U1.19@598.72,1138.85 598.72,1186.63
  other v1: 1260,34.91 2430,34.91 1590,39.91 1485,44.91 2150,44.91 2720,44.91 1090,49.91 3245,49.91 3625,49.91 225,54.91 1820,54.91 3065,59.91 345,64.91 3830,64.91 80,84.91 1828.62,154.91 2228.62,154.91 2428.62,154.91 2628.62,154.91 2828.62,154.91 3228.62,154.91 3428.62,154.91 3628.62,154.91 3885,194.91 55,234.91 306,260.91 930,289.91 455,299.91 1220,304.91 795,309.91 3110,346.36 210,352.91 328.62,354.91 528.62,354.91 928.62,354.91 1128.62,354.91 1328.62,354.91 1528.62,354.91 1728.62,354.91 1928.62,354.91 2128.62,354.91 2328.62,354.91 2528.62,354.91 2728.62,354.91 2928.62,354.91 3328.62,354.91 3528.62,354.91 3728.62,354.91 855,359.91 111,362.91 430,369.91 590,369.91 3845,419.91 1190,439.91 3895,524.91 601,528.91 536,529.91 950,529.91 2525,529.91 474,530.91 1228.62,554.91 1428.62,554.91 1628.62,554.91 1828.62,554.91 2028.62,554.91 2228.62,554.91 2428.62,554.91 2628.62,554.91 2828.62,554.91 3228.62,554.91 3428.62,554.91 3628.62,554.91 391,559.91 1015,574.91 390,626.91 3110,634.91 3905,674.91 1055,684.91 928.62,754.91 1328.62,754.91 1528.62,754.91 1728.62,754.91 1928.62,754.91 2128.62,754.91 2528.62,754.91 2728.62,754.91 2928.62,754.91 3328.62,754.91 3528.62,754.91 406,766.91 660,774.91 775,779.91 1050,804.91 3110,819.91 3905,829.91 865,834.91 930,879.91 406,888.91 750,889.91 655,899.91 2510,919.91 3590,924.91 1028.62,954.91 1428.62,954.91 1628.62,954.91 1828.62,954.91 2028.62,954.91 2228.62,954.91 2428.62,954.91 2628.62,954.91 2828.62,954.91 3228.62,954.91 3428.62,954.91 3628.62,954.91 1270,964.91 390,971.91 290,974.91 785,994.91 40,1014.91 950,1029.91 3630,1039.91 3910,1059.91 3110,1069.91 395,1074.91 168.1,1078.91 250,1079.91 315,1079.91 3605,1084.91 1060,1099.91 94,1112.91 245,1129.91 3370,1144.91 328.62,1154.91 1328.62,1154.91 1528.62,1154.91 1728.62,1154.91 1928.62,1154.91 2128.62,1154.91 2528.62,1154.91 2728.62,1154.91 2928.62,1154.91 207,1169.91 3220,1179.91 350,1204.91 3490,1219.91 116,1223.91 1050,1254.91 860,1259.91 2510,1284.91 3110,1284.91 1260,1289.91 590,1299.91 520,1329.91 960,1329.91 95,1334.91 175,1334.91 310,1344.91 570,1344.91 228.62,1354.91 428.62,1354.91 1028.62,1354.91 1828.62,1354.91 2028.62,1354.91 2228.62,1354.91 2628.62,1354.91 2828.62,1354.91 3028.62,1354.91 3228.62,1354.91 3428.62,1354.91 3885,1359.91 720,1404.91 260,1414.91 3505,1439.91 210,1444.91 960,1444.91 100,1459.91 295,1459.91 35,1464.91 670,1469.91 755,1469.91 2495,1469.91 560,1484.91 2355,1484.91 2200,1489.91 2900,1489.91 155,1494.91 2670,1494.91 3010,1494.91 2785,1499.91 455,1504.91 3110,1509.91 3365,1509.91 835,1524.91 65,1529.91 405,1534.91 3225,1539.91 1928.62,1554.91 2128.62,1554.91 3728.62,1554.91 640,1559.91 735,1559.91 795,1604.91 685,1609.91 2640,1609.91 2245,1614.91 2965,1614.91 3110,1614.91 2050,1619.91 2755,1619.91 340,1629.91 425,1629.91 1935,1637.91 750,1649.91 3850,1649.91 2165,1669.91 1120,1679.91 1270,1679.91 2495,1704.91 340,1719.91 430,1719.91 2350,1719.91 1520,1729.91 1600,1734.91 1670,1739.91 2465,1744.91 1931,1759.91 3490,1779.91 1285,1784.91 1520,1784.91 2085,1784.91 1590,1789.91 3835,1789.91 3111,1800.91 2030,1804.91 2355,1814.91 290,1819.91 430,1819.91 2465,1819.91 365,1824.91 3590,1829.91 1245,1859.91 1180,1864.91 1095,1869.91 2015,1879.91 2355,1889.91 2465,1889.91 2100,1904.91 1925,1909.91 3885,1914.91 365,1919.91 435,1924.91 2500,1924.91 1615,1939.91 1665,1939.91 1964,1951.91 1128.62,1954.91 2350,1954.91 2528.62,1954.91 2620,1954.91 3728.62,1954.91 1008,1958.91 3190,1964.91 1450,1989.91 1270,2004.91 2855,2009.91 1845,2014.91 1065,2018.91 2412,2019.91 3845,2024.91 2275,2029.91 1185,2034.91 435,2059.91 1465,2059.91 3660,2059.91 380,2064.91 1535,2064.91 875,2079.91 1920,2079.91 980,2082.91 740,2084.91 2340,2094.91 2775,2094.91 1075,2104.91 1720,2104.91 2405,2114.91 1865,2119.91 390,2129.91 828.62,2154.91 3228.62,2154.91 3428.62,2154.91 3105,2159.91 2345,2174.91 2435,2174.91 2520,2174.91 2605,2174.91 585,2179.91 645,2179.91 745,2179.91 1860,2179.91 3835,2179.91 1550,2189.91 1360,2194.91 1455,2194.91 1605,2194.91 435,2199.91 90,2229.91 285,2229.91 3320,2239.91 485,2254.91 3160,2259.91 3030,2274.91 2220,2279.91 2355,2283.92 2465,2284.91 3875,2329.91 328.62,2354.91 2128.62,2354.91 2728.62,2354.91 2928.62,2354.91 3328.62,2354.91 3528.62,2354.91 3885,2394.91 50,2409.91 3140,2414.91 295,2474.91 2415,2479.91 3215,2489.91 3340,2489.91 3820,2489.91 1840,2494.91 3575,2494.91 3755,2494.91 2680,2499.91 2970,2504.91 1075,2514.91 1255,2514.91 1500,2514.91 565,2519.91 825,2519.91
  other v2: 1333,1665.91 1280,1921.91 1142,2150.91 1084,2151.91 1210,2152.91
  other v3: 2650,1764.91 2575,1769.91 2610,1809.91 2575,1854.91 2645,1854.91
AP3V3: C22.1 C23.2 L3.2 U3.44 | length 280.2
  Top Layer w9: U3.44@1595.47,2000.26 1595.47,2054.43
  Top Layer w20: L3.2@1490.51,2129.91 1510.51,2109.91 C22.1@1550.75,2109.91 ; L3.2@1499.88,2132.48 ccw(c1550.74,2178.49) C22.1@1550.75,2109.91 ; 1595.75,2054.71 C23.2@1595.75,2109.91 C22.1@1550.75,2109.91
AUART0_TX: J3.19
AUART1_RX: J3.18
AUART1_TX: J3.17
AUART2_RX: J3.16
AUART2_TX: J3.15
AUART3_RX: J3.14
AUART3_TX: J3.13
AUART4_RX: J3.12
AUART4_TX: J3.11
CAN0_RX: J3.10
CAN0_TX: J3.9
CAN1_RX: J3.8
CAN1_TX: J3.7
CP_DP3V3: C2.2 C4.1 LED8.1 LED9.1 R9.2 U5.6 | length 1473.8
  Top Layer w10: U5.6@2709.49,1849.28 2745,1849.28
  Top Layer w15: LED9.1@1920,2194.43 v1(1975,2194.43) LED8.1@2030,2194.43 ; LED9.1@1925.83,2188.6 cw(c1939.91,2174.52) 1939.91,2194.43 cw(c1939.91,2214.35) LED9.1@1925.83,2200.27 ; LED8.1@2024.17,2188.6 ccw(c2010.09,2174.52) 2010.09,2194.43 ccw(c2010.09,2214.35) LED8.1@2024.17,2200.27 ; R9.2@2655,2039.91 C2.2@2700,2039.91 v1(2745,2039.91) ; 2745,1849.28 2779.37,1849.28 C4.1@2780,1849.91 v1(2780,1879.91)
  Bottom Layer w15: v1(1975,2194.43) 2099.53,2194.43 2110,2204.91 2572.48,2204.91 2578.98,2211.41 2723.5,2211.41 2745,2189.91 2745,1914.91 v1(2780,1879.91)
DP3V3: C3.1 C7.1 C15.1 C19.1 C21.2 J7.3 L3.1 LED0.1 LED1.1 LED2.1 LED3.1 LED4.1 LED5.1 LED6.1 LED7.1 R1.2 R13.1 R15.2 R17.2 R19.1 R20.1 R22.1 S1.2 S1.6 U3.8 U4.3 U7.5 | length 11098
  Top Layer w9: 1405,1805.38 U3.8@1459.65,1805.38
  Top Layer w15: C7.1@1314.67,2149.6 C15.1@1359.67,2149.6 ; v1(1365,1739.91) C19.1@1365,1774.91 1374.53,1774.91 1405,1805.38 ; C19.1@1365,1780.2 ccw(c1365,1815.99) 1390.3,1790.68 ; 1391.23,2149.6 cw(c1391.23,2111.97) L3.1@1420.4,2135.73 ; L3.1@1408.77,2126.26 ccw(c1359.67,2086.28) C15.1@1359.67,2149.6 ; L3.1@1420.51,2129.91 1400.82,2149.6 C15.1@1359.67,2149.6 ; 1655,2234.91 1655,2169.91 1670,2154.91 R1.2@1705,2154.91 ; R15.2@2043.43,1992.35 ccw(c2055.12,2004.04) 2055.12,1987.51 ; R15.2@2050,1999.91 2062.4,1987.51 U7.5@2120,1987.51 2127.6,1987.51 2160,2019.91 2160,2086.91 2137,2109.91 2080,2109.91 2070,2119.91 2070,2156.91 2090.5,2177.41 ; R15.2@2054.03,2002.96 ccw(c2091.33,2040.25) 2091.33,1987.51 ; R15.2@2055.3,1999.91 ccw(c2068.08,1999.91) R15.2@2059.04,1990.87 ; 2082.57,2169.48 cw(c2104.02,2148.03) R13.1@2104.02,2178.36 ; 2090.5,2186.12 ccw(c2104.7,2186.12) R13.1@2101.92,2172.19 ; R13.1@2101.88,2178.93 ccw(c2097.18,2170.72) 2090.5,2177.41 ; R13.1@2104.86,2186.9 cw(c2108.35,2204.41) 2090.5,2204.41 2090.5,2177.41 ; U7.5@2132.5,1987.51 cw(c2144.33,1987.51) 2135.97,1995.87 ; R17.2@2353.43,1992.35 ccw(c2377.43,2016.35) 2377.43,1982.41 ; R17.2@2360,1999.91 2377.5,1982.41 U4.3@2460,1982.41 2497.5,2019.91 2520,2019.91 2540,2039.91 C21.2@2565,2039.91 v1(2565,2234.91) ; R17.2@2364.03,2002.96 ccw(c2413.64,2052.56) 2413.64,1982.41 ; R17.2@2365.3,1999.91 ccw(c2378.08,1999.91) R17.2@2369.04,1990.87 ; U4.3@2452.58,1974.98 ccw(c2434.65,1957.06) 2434.65,1982.41 ccw(c2434.65,2007.76) U4.3@2452.58,1989.83 ; U4.3@2460,1994.91 ccw(c2460,2025.08) 2481.34,2003.75 ; U4.3@2470.5,1984.41 cw(c2491.02,1984.41) U4.3@2476.51,1998.92 ; 3195,1704.91 3185.62,1704.91 3200.62,1719.91 ; 3200.62,1704.6 ccw(c3223.75,1704.6) R22.1@3207.4,1688.25 ; R22.1@3203.27,1688.25 ccw(c3187.02,1704.5) 3210,1704.5 ; R20.1@3340,1684.91 R19.1@3295,1684.91 3295,1729.91 3280,1744.91 3225.62,1744.91 3210,1729.28 ; 3200.62,1719.91 3210,1729.28 ; 3200.62,1719.91 3200.62,1689.91 R22.1@3205.33,1685.2 3210,1689.86 3210,1729.28
  Top Layer w25: LED0.1@530.47,1574.91 LED1.1@530.47,1654.91 LED2.1@530.47,1734.91 LED3.1@530.47,1814.91 LED4.1@530.47,1894.91 LED5.1@530.47,1974.91 LED6.1@530.47,2054.91 LED7.1@530.47,2134.91 530.47,2190.38 575,2234.91 1285,2234.91 ; C7.1@1314.67,2149.6 1314.67,2205.24 ; 2099.38,2195.53 cw(c2086.52,2182.67) R13.1@2104.7,2182.67 ; R13.1@2105,2189.91 2090.5,2204.41 v1(2060,2234.91) v1(2025,2234.91) 1655,2234.91 1344.34,2234.91 ; C3.1@3064.41,1699.91 3079.12,1685.2 R22.1@3205.33,1685.2 ; C3.1@3065,1684.91 3085,1704.91 3185.62,1704.91 R22.1@3200.62,1689.91 ; C3.1@3073.68,1708.19 ccw(c3129.18,1763.7) 3129.18,1685.2 ; C3.1@3102.64,1717.89 ccw(c3131.59,1758.85) v1@3140.08,1709.41 ; 3118.51,1685.2 ccw(c3118.51,1646.79) 3091.35,1673.95 cw(c3166.1,1599.2) 3166.1,1704.91 ; 3129.54,1695.69 ccw(c3118.01,1715.94) v1@3140.48,1709.77 ; v1@3139.51,1709.8 ccw(c3161.67,1714.79) 3156.66,1692.64 ; v1@3139.58,1709.64 ccw(c3176.57,1732.98) 3166.91,1690.32 ; 3141.63,1697.64 cw(c3127.31,1672.13) v1@3155.48,1680.04 ; v1@3141.95,1704.91 cw(c3141.95,1776.47) 3091.35,1725.87 ccw(c3189.54,1824.05) 3189.54,1685.2 ; 3143.44,1685.2 cw(c3143.44,1668.34) v1@3155.35,1680.26 ; v1@3154.65,1680.26 cw(c3166.56,1668.34) 3166.56,1685.2 ; 3158.43,1704.91 cw(c3158.43,1639.28) R22.1@3204.84,1685.68 ; 1285,2234.91 1344.34,2234.91 ; 1285,2234.91 1314.67,2205.24 ; 1314.67,2205.24 1344.34,2234.91
  Bottom Layer w15: J7.3@110,2024.91 165.5,2080.41 340.5,2080.41 355,2094.91 v1(530.47,2094.91) ; J7.3@115,2047.41 ccw(c115,2089.66) 144.87,2059.78 ; J7.3@137.5,2024.91 cw(c203.89,2024.91) 156.95,2071.85 ; v1(1365,1739.91) 1400,1774.91 v1(1400,2234.91)
  Bottom Layer w25: v1(2025,2234.91) v1(2060,2234.91) 2063.5,2238.41 2881.5,2238.41 3148.74,1971.17 S1.6@3148.74,219.91 ; S1.2@3139.9,135.32 ccw(c3118.56,156.66) 3148.74,156.66 ccw(c3178.92,156.66) S1.2@3157.58,135.32 ; S1.6@3139.9,206.07 cw(c3118.56,184.73) 3148.74,184.73 cw(c3178.92,184.73) S1.6@3157.58,206.07 ; v1@3140.35,1709.55 ccw(c3120.11,1729.8) 3148.74,1729.8 ; v1@3140.35,1710.26 cw(c3120.11,1690.01) v1@3148.74,1690.01 ; S1.2@3148.74,121.48 S1.6@3148.74,219.91 ; v1@3148.74,1674.91 S1.6@3148.74,219.91 ; 3148.74,1693.81 ccw(c3168.91,1693.81) v1@3154.65,1679.55 ; 3148.74,255.08 cw(c3118.56,255.08) 3139.9,233.75 ccw(c3118.56,255.08) 3148.74,255.08 ; 3148.74,255.08 ccw(c3178.92,255.08) 3157.58,233.75 cw(c3178.92,255.08) 3148.74,255.08 ; 3148.74,1666 cw(c3168.91,1666) 3154.65,1680.26 ccw(c3168.91,1666) 3148.74,1666
  other v1: 3155,1679.91 3140,1709.91
DUART_TX: J3.21
ECLK: J7.7 U3.22 | length 2155.1
  Top Layer w7: v1(1005,1629.91) 1005,1564.91 1090,1479.91 1195.95,1479.91 1203.95,1471.91 1561,1471.91 1693.9,1604.8 U3.22@1693.9,1669.55
  Bottom Layer w7: J7.7@110,1824.91 160,1874.91 595,1874.91 840,1629.91 v1(1005,1629.91) ; J7.7@115,1844.41 ccw(c115,1879.41) 139.75,1854.66 ; J7.7@115,1851.41 ccw(c115,1903.31) 151.7,1866.61 ; J7.7@127.48,1825.6 cw(c163.04,1827.58) 137.86,1852.77 ; J7.7@134.47,1825.99 cw(c184.02,1828.75) 148.93,1863.84 ; J7.7@141.46,1826.38 cw(c204.99,1829.91) 160,1874.9 ; v1@998.99,1623.9 ccw(c984.48,1609.39) 984.48,1629.91 ccw(c984.48,1650.43) v1@998.99,1635.92
EIO0: J9.11 U3.15 | length 2811.6
  Top Layer w7: v1(1230,1539.91) 1491.1,1539.91 1556.1,1604.91 U3.15@1556.1,1669.55 ; v1@1236.01,1533.9 cw(c1250.52,1519.39) 1250.52,1539.91 cw(c1250.52,1560.43) v1@1236.01,1545.92
  Bottom Layer w7: J9.11@110,424.91 157,377.91 261,377.91 308,424.91 1013.99,424.91 1210,620.91 1210,1519.91 v1(1230,1539.91) ; J9.11@115,398.41 cw(c115,346.5) 151.7,383.2 ; J9.11@115,405.41 cw(c115,370.4) 139.75,395.15 ; J9.11@127.43,423.59 ccw(c157.97,420.37) 136.26,398.65 ; J9.11@134.39,422.86 ccw(c176.73,418.39) 146.63,388.28 ; J9.11@141.35,422.12 ccw(c195.49,416.41) 157,377.91 ; v1@1221.5,1539.91 cw(c1200.98,1539.91) 1215.49,1525.4 cw(c1230,1510.89) v1@1230,1531.41
EIO1: J9.9 U3.13 | length 2778.4
  Top Layer w7: v1(1190,1569.91) 1200,1579.91 ; v1@1192.49,1578.03 ccw(c1194.69,1585.22) 1200,1579.91 ; v1@1198.13,1572.39 cw(c1205.31,1574.59) 1200,1579.91 ; U3.13@1516.73,1669.55 1516.73,1607.64 1489,1579.91 1200,1579.91
  Bottom Layer w7: J9.9@110,524.91 159,475.91 277,475.91 309,443.91 1013.2,443.91 1190,620.71 v1(1190,1569.91) ; J9.9@115,498.41 cw(c115,446.5) 151.7,483.2 ; J9.9@115,505.41 cw(c115,470.4) 139.75,495.15 ; J9.9@127.47,524.01 ccw(c161.33,521.59) 137.32,497.58 ; J9.9@134.45,523.51 ccw(c181.55,520.14) 148.16,486.75 ; J9.9@141.43,523.01 ccw(c201.78,518.69) 159,475.91 ; v1@1183.99,1563.9 cw(c1169.48,1549.39) 1190,1549.39 cw(c1210.52,1549.39) v1@1196.01,1563.9
EIO2: J9.7 U3.26 | length 3155
  Top Layer w7: v1(1155,1394.91) 1577,1394.91 1845,1662.91 1845,1734.91 1833.58,1746.32 U3.26@1790.35,1746.32 ; v1@1161.01,1388.9 cw(c1175.52,1374.39) 1175.52,1394.91 cw(c1175.52,1415.43) v1@1161.01,1400.92
  Bottom Layer w7: J9.7@110,624.91 160,574.91 244,574.91 361,457.91 1007.4,457.91 1155,605.51 v1(1155,1394.91) ; J9.7@115,598.41 cw(c115,546.5) 151.7,583.2 ; J9.7@115,605.41 cw(c115,570.4) 139.75,595.15 ; J9.7@127.48,624.21 ccw(c163.04,622.24) 137.86,597.05 ; J9.7@134.47,623.82 ccw(c184.02,621.07) 148.93,585.98 ; J9.7@141.46,623.44 ccw(c204.99,619.9) 160,574.91 ; v1@1148.99,1388.9 cw(c1134.48,1374.39) 1155,1374.39 cw(c1175.52,1374.39) v1@1161.01,1388.9
EIO3: J9.5 U3.38 | length 3406.7
  Top Layer w7: v1(1155,1439.91) 1578,1439.91 1761.48,1623.39 1761.48,1697.11 1735,1723.6 1735,1928.49 1713.58,1949.91 U3.38@1713.58,2000.26 ; v1@1161.01,1433.9 cw(c1175.52,1419.39) 1175.52,1439.91 cw(c1175.52,1460.43) v1@1161.01,1445.92
  Bottom Layer w7: J9.5@110,724.91 159,675.91 257,675.91 286,646.91 286,569.31 383.4,471.91 1001.6,471.91 1132.5,602.81 1132.5,1417.41 v1(1155,1439.91) ; J9.5@115,698.41 cw(c115,646.5) 151.7,683.2 ; J9.5@115,705.41 cw(c115,670.4) 139.75,695.15 ; J9.5@127.47,724.01 ccw(c161.33,721.59) 137.32,697.58 ; J9.5@134.45,723.51 ccw(c181.55,720.14) 148.16,686.75 ; J9.5@141.43,723.01 ccw(c201.78,718.69) 159,675.91 ; v1@1146.5,1439.91 cw(c1125.98,1439.91) 1140.49,1425.4 cw(c1155,1410.89) v1@1155,1431.41
EIO5: J9.3 U3.21 | length 3108.6
  Top Layer w7: v1(1141,1502.91) 1160.5,1502.91 1167.5,1495.91 1199.75,1495.91 1209.75,1485.91 1551,1485.91 1674.21,1609.12 U3.21@1674.21,1669.55 ; v1@1147.23,1497.12 cw(c1160.5,1484.79) 1160.5,1502.91 cw(c1160.5,1521.02) v1@1147.23,1508.69
  Bottom Layer w7: J9.3@110,824.91 157,777.91 284,777.91 300,761.91 300,575.11 389.2,485.91 995.8,485.91 1118.5,608.61 1118.5,1480.41 v1(1141,1502.91) ; J9.3@115,798.41 cw(c115,746.5) 151.7,783.2 ; J9.3@115,805.41 cw(c115,770.4) 139.75,795.15 ; J9.3@127.43,823.59 ccw(c157.97,820.37) 136.26,798.65 ; J9.3@134.39,822.86 ccw(c176.73,818.39) 146.63,788.28 ; J9.3@141.35,822.12 ccw(c195.49,816.41) 157,777.91 ; v1@1132.5,1502.91 cw(c1111.98,1502.91) 1126.49,1488.4 cw(c1141,1473.89) v1@1141,1494.41
ERR: J3.5
ERST: J7.11 U3.14 | length 1846.9
  Top Layer w7: v1@1070,1571.41 cw(c1070,1550.89) 1084.51,1565.4 cw(c1099.02,1579.91) v1@1078.5,1579.91 ; v1(1070,1579.91) 1086,1563.91 1164.18,1563.91 1180.68,1547.41 1202.5,1547.41 1220,1564.91 1493.8,1564.91 1536.42,1607.53 U3.14@1536.42,1669.55
  Bottom Layer w7: J7.11@110,1624.91 160,1674.91 685,1674.91 782.5,1577.41 1067.5,1577.41 v1(1070,1579.91) ; J7.11@115,1644.41 ccw(c115,1679.41) 139.75,1654.66 ; J7.11@115,1651.41 ccw(c115,1703.31) 151.7,1666.61 ; J7.11@127.48,1625.6 cw(c163.04,1627.58) 137.86,1652.77 ; J7.11@134.47,1625.99 cw(c184.02,1628.75) 148.93,1663.84 ; J7.11@141.46,1626.38 cw(c204.99,1629.91) 160,1674.9 ; 1043.44,1577.41 ccw(c1043.44,1606.46) v1@1063.99,1585.92 ; 1055.51,1577.41 cw(c1055.51,1565.42) v1@1063.99,1573.9
ESDI: J7.5 U3.28 | length 2690
  Top Layer w7: v1@923.99,1648.9 cw(c909.48,1634.39) 930,1634.39 cw(c950.52,1634.39) v1@936.01,1648.9 ; v1(930,1654.91) 930,1633.91 920,1623.91 920,1567.23 1128.83,1358.41 1587.5,1358.41 1875,1645.91 1875,1754.91 1844.21,1785.69 U3.28@1790.35,1785.69
  Bottom Layer w7: J7.5@110,1924.91 160,1974.91 515,1974.91 835,1654.91 v1(930,1654.91) ; J7.5@115,1944.41 ccw(c115,1979.41) 139.75,1954.66 ; J7.5@115,1951.41 ccw(c115,2003.31) 151.7,1966.61 ; J7.5@127.48,1925.6 cw(c163.04,1927.58) 137.86,1952.77 ; J7.5@134.47,1925.99 cw(c184.02,1928.75) 148.93,1963.84 ; J7.5@141.46,1926.38 cw(c204.99,1929.91) 160,1974.9 ; v1@923.99,1648.9 ccw(c909.48,1634.39) 909.48,1654.91 ccw(c909.48,1675.43) v1@923.99,1660.92
ESDO: J7.9 U3.27 | length 2504.1
  Top Layer w7: v1@938.99,1593.9 cw(c924.48,1579.39) 945,1579.39 cw(c965.52,1579.39) v1@951.01,1593.9 ; v1(945,1599.91) 945,1562.03 1134.62,1372.41 1579.5,1372.41 1860,1652.91 1860,1744.91 1838.9,1766.01 U3.27@1790.35,1766.01
  Bottom Layer w7: J7.9@110,1724.91 160,1774.91 665,1774.91 840,1599.91 v1(945,1599.91) ; J7.9@115,1744.41 ccw(c115,1779.41) 139.75,1754.66 ; J7.9@115,1751.41 ccw(c115,1803.31) 151.7,1766.61 ; J7.9@127.48,1725.6 cw(c163.04,1727.58) 137.86,1752.77 ; J7.9@134.47,1725.99 cw(c184.02,1728.75) 148.93,1763.84 ; J7.9@141.46,1726.38 cw(c204.99,1729.91) 160,1774.9 ; v1@938.99,1593.9 ccw(c924.48,1579.39) 924.48,1599.91 ccw(c924.48,1620.43) v1@938.99,1605.92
